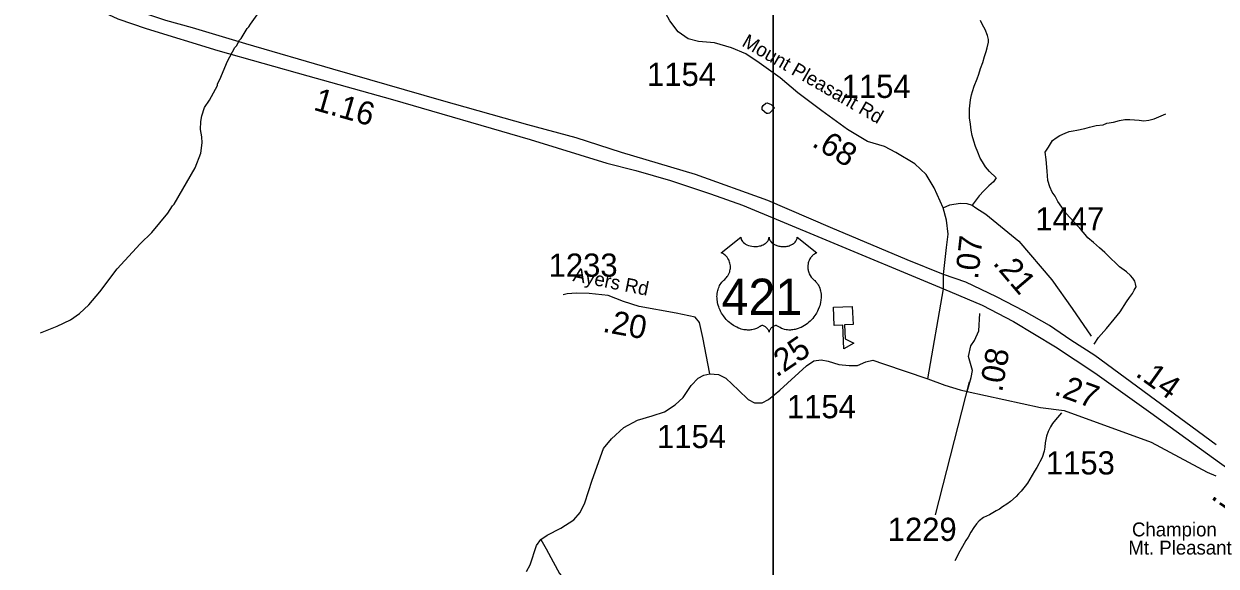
# Model space of a CAD drawing. Extents: x 1248089 to 1457196, y 820910 to 988753.
# Drawn here: x 1308985 to 1315415, y 879960 to 882884 of the extents above; entities that cross this region are included whole.
import ezdxf

# ---------------------------------------------------------------- set-up
doc = ezdxf.new("R2010")
doc.units = 0
for name, color, linetype in [('Exist Cultural Educational Facility High CELL', 7, 'Continuous'), ('Exist Hydrographic Misc Water Feature', 7, 'Continuous'), ('Exist Road Non-System Type 51', 7, 'Continuous'), ('Exist Road Primary US Divided Attributed', 7, 'Continuous'), ('Exist Road Primary US Mileage Hundredths English Label', 7, 'Continuous'), ('Exist Road Primary US Shield Number Label', 7, 'Continuous'), ('Exist Road Secondary Type 51 Attributed', 7, 'Continuous'), ('Exist Road Secondary Type 51 Label', 7, 'Continuous'), ('Map Preparation Inset Cut Line', 7, 'Continuous'), ('Prop GRAU CAT1 Cell', 7, 'Continuous'), ('Prop Horizontal Alignment Direction Label', 7, 'Continuous'), ('Prop Lane Lines', 7, 'Continuous')]:
    doc.layers.add(name, color=color, linetype=linetype)

msp = doc.modelspace()

# ---------------------------------------------------------------- linework, layer by layer
at = {"layer": 'Exist Cultural Educational Facility High CELL'}
msp.add_lwpolyline([(1313452.7, 881359.9), (1313456.6, 881262.1), (1313410.6, 881260.3), (1313413.6, 881185.2), (1313461.5, 881162.9), (1313406.1, 881131.5), (1313401, 881259.9), (1313355, 881258.1), (1313351.1, 881355.9)], close=True, dxfattribs=at)
at = {"layer": 'Exist Hydrographic Misc Water Feature'}
for points in [[(1309075.3, 881217.8), (1309164.3, 881253.1), (1309237.3, 881287.1), (1309286.3, 881321.6), (1309335.6, 881368.2), (1309395.6, 881438.4), (1309489.2, 881563.7), (1309613, 881698.1), (1309674.8, 881758.3), (1309761.7, 881863.7), (1309786.8, 881902.9), (1309795, 881910.7), (1309908.6, 882107.4), (1309938.9, 882186.5), (1309946.5, 882242.2), (1309945.3, 882274.3), (1309938.5, 882314.5), (1309939.7, 882356.4), (1309944.5, 882388.3), (1309959.8, 882431.8), (1309987, 882473), (1310029.2, 882551.7), (1310029.4, 882559.7), (1310042.1, 882583.4), (1310082.8, 882682.1), (1310123, 882757), (1310131.2, 882764.8), (1310148.1, 882796.2), (1310156.3, 882804), (1310189.8, 882859), (1310198.1, 882866.8), (1310206.6, 882882.5), (1310252.3, 882945.2)], [(1313032.7, 882430.9), (1313006.2, 882401.7), (1312998.1, 882400), (1312990.1, 882400.2), (1312966.8, 882420.9), (1312967.1, 882434.8), (1312971.4, 882442.7), (1312985.7, 882456.3), (1312993.7, 882458.1), (1313015.6, 882449.4), (1313032.7, 882430.9)]]:
    msp.add_lwpolyline(points, dxfattribs=at)
at = {"layer": 'Exist Road Non-System Type 51'}
for points in [[(1314227.9, 882053.3), (1314192.6, 882088.1), (1314171.2, 882112.7), (1314153.8, 882139.1), (1314142.4, 882159.3), (1314129, 882191.6), (1314117.8, 882222), (1314108.4, 882250.3), (1314099, 882282.5), (1314093.8, 882310.6), (1314090.4, 882342.7), (1314085.3, 882376.8), (1314083.8, 882402.8), (1314084.4, 882424.8), (1314089.6, 882474.8), (1314096.2, 882500.6), (1314100.5, 882518.6), (1314109.3, 882548.4), (1314126.1, 882588.1), (1314134.8, 882611.9), (1314143.5, 882643.6), (1314156.3, 882675.3), (1314164.9, 882707.2), (1314173.7, 882735), (1314180.1, 882754.9), (1314186.9, 882784.8), (1314187.2, 882798.8), (1314181.6, 882820.9), (1314168.5, 882853.2), (1314154.9, 882877.5), (1314143.4, 882901.9)], [(1314493.2, 882191.3), (1314510, 882218.8), (1314532.7, 882254.3), (1314551, 882270), (1314571.5, 882281.4), (1314599.8, 882294.8), (1314621.9, 882302.4), (1314644, 882307.7), (1314664.1, 882311.3), (1314706.3, 882320.3), (1314732.5, 882325.8), (1314766.9, 882334.9), (1314805, 882340.1), (1314825.2, 882347.5), (1314861.3, 882352.8), (1314893.5, 882362), (1314921.6, 882367.4), (1314949.7, 882368.6), (1314973.6, 882366.2), (1314999.6, 882363.6), (1315025.5, 882360.9), (1315051.6, 882364.4), (1315079.8, 882371.6), (1315142.6, 882398.2)], [(1314757.5, 881156.4), (1314780.2, 881191.9), (1314823.4, 881240.9), (1314864.6, 881291.9), (1314897.4, 881331.3), (1314930.7, 881384.4), (1314947.4, 881408.1), (1314963.9, 881429.8), (1314972.2, 881447.6), (1314982.8, 881465.4), (1314979.1, 881481.5), (1314975.4, 881495.6), (1314965.7, 881511.8), (1314952.2, 881526.1), (1314930.6, 881546.5), (1314893.1, 881573.5), (1314873.7, 881593.9), (1314846.2, 881618.7), (1314815, 881651.3), (1314785.5, 881676.1), (1314754, 881704.8), (1314722.7, 881729.6), (1314709.1, 881747.9), (1314687.5, 881772.3), (1314648.6, 881815.4), (1314605.7, 881860.4), (1314582.3, 881894.9), (1314561.1, 881925.4), (1314545.7, 881953.9), (1314530.3, 881976.2), (1314516.9, 882004.5), (1314507.8, 882038.7), (1314503, 882088.8), (1314498.5, 882153.2), (1314493.2, 882191.3)], [(1314227.9, 882053.3), (1314213.2, 882031.6), (1314188.8, 882010.1), (1314162.2, 881982.8), (1314137.5, 881957.3), (1314098.2, 881905.9)], [(1314580.7, 880786.3), (1314547.8, 880748.9), (1314531.4, 880729.4), (1314520.8, 880711.6), (1314508.3, 880685.9), (1314499.7, 880660), (1314492.8, 880624.2), (1314490.4, 880602.2), (1314487.7, 880580.2), (1314477.1, 880546.4), (1314464.4, 880522.9), (1314458.1, 880511), (1314447.7, 880491.2), (1314435.3, 880471.4), (1314422.7, 880449.7), (1314410.3, 880429.9), (1314397.6, 880408.3), (1314385.3, 880390.6), (1314362.8, 880365), (1314348.4, 880349.3), (1314336, 880335.7), (1314305.4, 880308.3), (1314285.1, 880294.7), (1314262.6, 880279.4), (1314246.3, 880267.7), (1314228.1, 880258), (1314191.7, 880237), (1314175.5, 880229.3), (1314159.2, 880221.6), (1314136.8, 880204.2), (1314122.5, 880188.5), (1314108.1, 880168.8), (1314091.3, 880143.1), (1314076.8, 880115.6), (1314064.2, 880097.8), (1314047.6, 880066.2), (1314032.8, 880040.4), (1314005.8, 879989.1)], [(1311773.3, 880103.5), (1311802.7, 880053.9), (1311839.1, 879983.4), (1311873.1, 879920.3), (1311892.5, 879898.4), (1311928.9, 879881.4), (1312016.3, 879854.7), (1312035.7, 879842.6), (1312057.5, 879830.4), (1312084.2, 879786.7), (1312123, 879696.8), (1312174, 879534.1), (1312212.8, 879463.7), (1312251.7, 879410.2), (1312273.8, 879385.1)]]:
    msp.add_lwpolyline(points, dxfattribs=at)
at = {"layer": 'Exist Road Primary US Divided Attributed'}
for points in [[(1313944.8, 881532.7), (1313748.4, 881611.7), (1313334.9, 881785), (1312997, 881931.7), (1312607, 882070.9), (1312208.1, 882189.7), (1311963.9, 882269.7), (1311703.7, 882338.9), (1311236.7, 882470.7), (1310651.9, 882638.7), (1310182.3, 882775.5), (1309894.1, 882862.5), (1309750.9, 882901.6), (1309539.7, 882971.3), (1309323.6, 883058.3), (1309124.8, 883152.8), (1308953.4, 883237.3), (1308762.1, 883359.1), (1308498.7, 883533.2), (1308244.1, 883707.8)], [(1308208.6, 883633), (1308482.8, 883455.6), (1308712.5, 883311.4), (1308937.6, 883178.5), (1309095.2, 883090.7), (1309205.6, 883036.6), (1309340.7, 882980.3), (1309491.5, 882910.5), (1309644.6, 882858.7), (1310031.9, 882739.3), (1310516, 882604.1), (1310973, 882475.7), (1311716, 882259.5), (1312128.1, 882133.3), (1312285.7, 882092.8), (1312472.6, 882038.7), (1312688.7, 881966.7), (1312859.8, 881905.8), (1313287.6, 881727.9), (1313944.5, 881454.5)], [(1315415.2, 880614.4), (1314759.6, 881095.8), (1314630.4, 881177.9), (1314516.1, 881257.4), (1314379.5, 881334.5), (1314230.4, 881411.6), (1314064, 881491.1), (1313944.8, 881532.7)], [(1313944.5, 881454.5), (1314152.2, 881367.5), (1314321.1, 881279.6), (1314548.5, 881142.2), (1314760.1, 881002.6)], [(1314760.1, 881002.6), (1315061.8, 880786.3), (1315302.8, 880612.9), (1315575.2, 880416.9), (1315744.1, 880308.8), (1315793.6, 880279.5)]]:
    msp.add_lwpolyline(points, dxfattribs=at)
at = {"layer": 'Exist Road Secondary Type 51 Attributed'}
for points in [[(1313942.6, 881891.9), (1313894.8, 881998.9), (1313850.6, 882071.8), (1313788.9, 882129.2), (1313688, 882190.4), (1313625.9, 882222.8), (1313534, 882250.1), (1313427.1, 882314.8), (1313288.9, 882415.4), (1313159.7, 882512.4), (1313062.8, 882592), (1312951, 882674), (1312879, 882721.3), (1312801.9, 882753.6), (1312710, 882781), (1312623.1, 882788.4), (1312568.4, 882803.3), (1312513.7, 882840.6), (1312469, 882900.3), (1312332.4, 883151.4), (1312252.7, 883235.7)], [(1313942.6, 881891.9), (1313977.7, 881907.8), (1314033.4, 881917.4), (1314070, 881915.8), (1314098.2, 881905.9), (1314119.4, 881891.9), (1314171.9, 881858.4), (1314350.7, 881711.6), (1314528, 881503.3), (1314638.9, 881348.6), (1314739.8, 881200.8)], [(1313944.8, 881532.7), (1313961.3, 881678.5), (1313969.5, 881750), (1313961.3, 881825.6), (1313942.6, 881891.9)], [(1313944.5, 881454.5), (1313944.8, 881532.7)], [(1313860.4, 880969.5), (1313944.5, 881454.5)], [(1312684.2, 880996.5), (1312647.5, 881193.3), (1312628.3, 881274.4), (1312604.8, 881302.2), (1312502.4, 881323.5), (1312304, 881359.8), (1312218.6, 881387.6), (1312135.4, 881419.6), (1312033, 881430.3), (1311964.7, 881432.4), (1311915.6, 881428.1), (1311893.1, 881422.5)], [(1314072.6, 880901.2), (1314094.4, 880977.7), (1314101.1, 881015.2), (1314079, 881090.3), (1314092, 881147), (1314112.1, 881176.4), (1314134.2, 881229.4), (1314140.8, 881322.1)], [(1312684.2, 880996.5), (1312731.8, 880993), (1312770.2, 880973.7), (1312838.4, 880909.7), (1312891.8, 880858.4), (1312925.9, 880841.4), (1312966.5, 880841.4), (1313000.6, 880858.4), (1313062.5, 880909.7), (1313205.4, 881039.9), (1313246, 881067.7), (1313284.4, 881072), (1313322.8, 881065.6), (1313380.4, 881046.3), (1313435.8, 881042.1), (1313480.6, 881042.1), (1313525.4, 881061.3), (1313563.9, 881069.8), (1313621.5, 881050.6), (1313860.4, 880969.5)], [(1311694.9, 879931.1), (1311716.3, 879966.3), (1311750.4, 880072), (1311773.3, 880103.5), (1311807.4, 880127), (1311881, 880164.3), (1311951.4, 880210.3), (1311984.5, 880249.8), (1312010.1, 880301), (1312050.6, 880423.8), (1312110.2, 880593.8), (1312155, 880647.1), (1312220.1, 880708), (1312294.7, 880746.4), (1312372.6, 880769.9), (1312439.4, 880792.8), (1312497, 880829.1), (1312540.7, 880869.7), (1312583.4, 880933.8), (1312621.8, 880974.3), (1312651.7, 880989.3), (1312684.2, 880996.5)], [(1313860.4, 880969.5), (1313951.2, 880935.3), (1314034.6, 880910.7), (1314072.6, 880901.2)], [(1314072.6, 880901.2), (1314467.2, 880815), (1314594.7, 880798.4), (1315064.2, 880627.7), (1315366.2, 880466.3), (1315412.1, 880447.6)]]:
    msp.add_lwpolyline(points, dxfattribs=at)
at = {"layer": 'Map Preparation Inset Cut Line'}
for points in [[(1313026.2, 913085.2), (1388709.5, 913085.2), (1388709.5, 884379.9), (1373500.6, 884376.6), (1373500.6, 868836.7), (1313026.2, 868836.7)], [(1313026.2, 867658.5), (1300766.9, 867658.5), (1300766.9, 889680.3), (1313026.2, 889680.3)]]:
    msp.add_lwpolyline(points, close=True, dxfattribs=at)
at = {"layer": 'Prop Horizontal Alignment Direction Label'}
msp.add_lwpolyline([(1312851.7, 881733.6), (1312852, 881729.2), (1312853, 881724), (1312853.9, 881721.3), (1312856.3, 881716.2), (1312860.3, 881710.1), (1312865.9, 881704.1), (1312872.3, 881698.9), (1312876.6, 881696.1), (1312883.8, 881692.2), (1312892, 881688.8), (1312901.2, 881686.1), (1312910.5, 881684.3), (1312920.8, 881683.1), (1312930.9, 881682.9), (1312941.8, 881683.7), (1312953.8, 881686.1), (1312959.4, 881687.5), (1312965.6, 881689.7), (1312971.4, 881692), (1312977.8, 881695.4), (1312982.8, 881698.7), (1312986.8, 881701.6), (1312992.5, 881707), (1312997, 881712.6), (1312998.9, 881715.7), (1313000.5, 881718.7), (1313002.7, 881725.1), (1313003.3, 881728), (1313003.8, 881733.8), (1313004.2, 881728.9), (1313004.7, 881725.8), (1313005.5, 881722.8), (1313006.7, 881719.6), (1313009, 881715.1), (1313011.5, 881711.3), (1313016.2, 881705.7), (1313019.2, 881703), (1313021.9, 881700.8), (1313029.1, 881695.8), (1313037.5, 881691.5), (1313041.7, 881689.7), (1313046, 881688.2), (1313051.4, 881686.6), (1313056.9, 881685.3), (1313062.5, 881684.3), (1313068.1, 881683.5), (1313073.9, 881683.1), (1313078.6, 881682.9), (1313084.4, 881683), (1313089.7, 881683.3), (1313095.2, 881683.9), (1313101.2, 881684.9), (1313106, 881686), (1313112.4, 881687.7), (1313118.2, 881689.8), (1313123.3, 881692), (1313129.9, 881695.4), (1313135.2, 881698.8), (1313139.1, 881701.9), (1313143.8, 881706.2), (1313148.1, 881711.3), (1313150.7, 881715), (1313152.5, 881718.8), (1313154.2, 881722.8), (1313155.3, 881727.1), (1313155.8, 881730.8), (1313155.9, 881734), (1313262.1, 881649.3), (1313259.6, 881648.3), (1313253.9, 881645.5), (1313249.3, 881642.8), (1313242, 881637.7), (1313238.8, 881634.8), (1313235.7, 881631.9), (1313232.8, 881628.7), (1313230.3, 881625.8), (1313227.2, 881621.5), (1313224.4, 881617.2), (1313221.7, 881612.5), (1313219.8, 881608.5), (1313216.5, 881599.9), (1313214.9, 881594.5), (1313213.9, 881589.9), (1313212.7, 881580.4), (1313212.4, 881575.9), (1313212.4, 881571.5), (1313212.6, 881566.8), (1313213, 881562.2), (1313213.9, 881557.5), (1313214.6, 881553.4), (1313215.9, 881548.3), (1313217.8, 881542.4), (1313220.1, 881536.7), (1313225, 881527.4), (1313231.2, 881518), (1313235.7, 881512.7), (1313240.1, 881508.2), (1313246.7, 881502.7), (1313250.2, 881499.6), (1313254.3, 881495.5), (1313260.9, 881487.8), (1313263.6, 881484.1), (1313266.4, 881480), (1313268.9, 881475.8), (1313271.4, 881471.3), (1313273.4, 881467.3), (1313277.1, 881458.2), (1313279.9, 881449.4), (1313281.1, 881444.7), (1313283.1, 881434.3), (1313283.8, 881429.2), (1313284.7, 881419), (1313284.7, 881406.7), (1313283.7, 881395), (1313281.6, 881381.4), (1313279.7, 881373.2), (1313276.9, 881363.7), (1313274.2, 881355.5), (1313269.4, 881343.4), (1313265.1, 881334.6), (1313259.5, 881324.3), (1313255.7, 881318.1), (1313251.2, 881311.4), (1313245.6, 881303.8), (1313239.1, 881295.6), (1313231.2, 881287), (1313224.9, 881280.6), (1313216.6, 881273.2), (1313211.6, 881269.1), (1313204.4, 881263.7), (1313194.7, 881257.2), (1313185, 881251.6), (1313176.8, 881247.4), (1313169.5, 881244.2), (1313160.1, 881240.6), (1313144.4, 881236.3), (1313138.7, 881235.1), (1313131.9, 881234.1), (1313125.5, 881233.5), (1313119.4, 881233.1), (1313111.1, 881233.1), (1313102.9, 881233.7), (1313095.1, 881234.9), (1313087, 881236.6), (1313078.5, 881239.1), (1313070.8, 881242.1), (1313063.1, 881245.9), (1313049.9, 881254.2), (1313046.1, 881256.2), (1313044, 881256.8), (1313038.9, 881257), (1313034.1, 881256), (1313029.2, 881254.1), (1313026.3, 881252.5), (1313022.4, 881249.9), (1313019.3, 881247.5), (1313015.7, 881244.1), (1313013.2, 881241.2), (1313011.3, 881238.9), (1313007.6, 881233.1), (1313006.3, 881230.3), (1313004.9, 881226.8), (1313003.7, 881221.5), (1313002, 881228.1), (1313000, 881232.5), (1312997.8, 881236.3), (1312995.4, 881239.6), (1312991.7, 881243.9), (1312988.4, 881247.1), (1312984.4, 881250.4), (1312980.1, 881252.9), (1312976.7, 881254.7), (1312973.6, 881255.9), (1312969.7, 881256.8), (1312966.6, 881257.1), (1312964, 881257), (1312960.5, 881256.2), (1312955.7, 881252.8), (1312951.1, 881249.6), (1312946.2, 881246.5), (1312940.3, 881243.4), (1312935.9, 881241.4), (1312930.8, 881239.4), (1312924.8, 881237.4), (1312918.2, 881235.7), (1312911.5, 881234.4), (1312905.6, 881233.4), (1312899.3, 881232.8), (1312893.6, 881232.7), (1312887.6, 881232.7), (1312882, 881233.2), (1312875.5, 881233.7), (1312867.5, 881234.9), (1312860.9, 881236.4), (1312853.8, 881238.3), (1312846.6, 881240.6), (1312838.9, 881243.5), (1312829.2, 881247.7), (1312822.5, 881251.2), (1312811.9, 881257.3), (1312799.5, 881265.9), (1312790.1, 881273.5), (1312783.2, 881279.7), (1312773.1, 881290), (1312767.2, 881296.7), (1312757.9, 881308.8), (1312751.9, 881317.5), (1312748, 881323.9), (1312742.4, 881334.2), (1312739.3, 881340.7), (1312735.3, 881350.1), (1312732.1, 881358.7), (1312729.5, 881366.9), (1312728.1, 881372.1), (1312726, 881381.2), (1312724.8, 881387.6), (1312723.6, 881396.5), (1312723, 881405.9), (1312722.8, 881414.5), (1312723.1, 881421.6), (1312723.9, 881430), (1312725.3, 881438.8), (1312727, 881446.4), (1312728.5, 881451.9), (1312730.8, 881458.5), (1312733.8, 881465.9), (1312737.3, 881472.9), (1312740.6, 881478.8), (1312744.8, 881485.1), (1312749, 881490.4), (1312754.4, 881496.3), (1312760.1, 881501.7), (1312765.2, 881505.9), (1312771.4, 881511.9), (1312774.6, 881515.6), (1312778.5, 881520.7), (1312781.5, 881525.4), (1312784, 881529.6), (1312787.2, 881535.8), (1312789.2, 881540.4), (1312791.6, 881547.6), (1312792.8, 881552.6), (1312794.1, 881559.1), (1312794.9, 881565.2), (1312795.2, 881572.8), (1312795, 881579.1), (1312794.2, 881586.4), (1312792.8, 881593.4), (1312791.2, 881599.6), (1312788.5, 881606.6), (1312786.1, 881611.8), (1312782, 881618.7), (1312777.5, 881625.2), (1312772.8, 881630.5), (1312768.1, 881635.2), (1312763.6, 881638.7), (1312759.3, 881641.8), (1312753.9, 881645.1), (1312748.7, 881647.6), (1312745.4, 881649)], close=True, dxfattribs=at)
at = {"layer": 'Prop Lane Lines'}
msp.add_line((1314082.3, 880953.6), (1313900, 880237.3), dxfattribs=at)

# ---------------------------------------------------------------- texts
at = {"layer": 'Exist Road Primary US Mileage Hundredths English Label'}
for s, rotation, p in [('1.16', 343.97125, (1310542.1, 882421.2)), ('.14', 324.3447, (1314974, 880988.8)), ('.10', 325.91786, (1315381.3, 880326.8))]:
    msp.add_text(s, height=125, rotation=rotation, dxfattribs=at).set_placement(p)
at = {"layer": 'Exist Road Primary US Shield Number Label'}
msp.add_text('421', height=195, dxfattribs=at).set_placement((1312747.8, 881314.9))
at = {"layer": 'Exist Road Secondary Type 51 Label'}
for s, rotation, p in [('Mount Pleasant Rd', 330.05354, (1312852.3, 882767.5)), ('Ayers Rd', 348.75858, (1311942.2, 881497.8))]:
    msp.add_text(s, height=75, rotation=rotation, dxfattribs=at).set_placement(p)
for s, p in [('Champion', (1314960.7, 880120.5)), ('Mt. Pleasant', (1314940.9, 880022.5))]:
    msp.add_text(s, height=75, dxfattribs=at).set_placement(p)
at = {"layer": 'Prop GRAU CAT1 Cell'}
for s, rotation, p in [('.68', 328.82035, (1313229, 882227.3)), ('.07', 83.54118, (1314130.1, 881502.9)), ('.21', 310.41124, (1314206.5, 881591.6)), ('.20', 349.63289, (1312102.1, 881224.3)), ('.25', 34.40133, (1313044.8, 880975.2)), ('.08', 79.99952, (1314259.9, 880894.6)), ('.27', 340.01301, (1314535.5, 880886.5))]:
    msp.add_text(s, height=125, rotation=rotation, dxfattribs=at).set_placement(p)
at = {"layer": 'Prop Lane Lines'}
for s, p in [('1154', (1312345.9, 882549)), ('1154', (1313395.1, 882484.1)), ('1447', (1314439.6, 881769.8)), ('1233', (1311815.1, 881520.4)), ('1154', (1313100, 880757.4)), ('1154', (1312400, 880596.6)), ('1153', (1314496.5, 880454.3)), ('1229', (1313643.7, 880096.1))]:
    msp.add_text(s, height=125, dxfattribs=at).set_placement(p)

doc.saveas('drawing.dxf')
